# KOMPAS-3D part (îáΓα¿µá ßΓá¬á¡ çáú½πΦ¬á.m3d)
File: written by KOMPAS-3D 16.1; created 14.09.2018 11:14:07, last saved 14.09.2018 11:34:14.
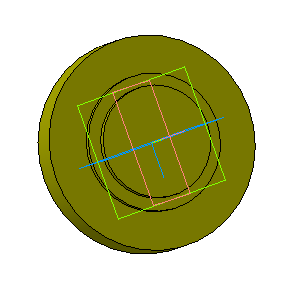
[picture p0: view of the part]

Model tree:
1. Эскиз:1
2. Операция вращения:1  (labels: Полипропилен  ГОСТ 26996-86)
     Угол 1 = 360

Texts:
  Линейный размер с обрывом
